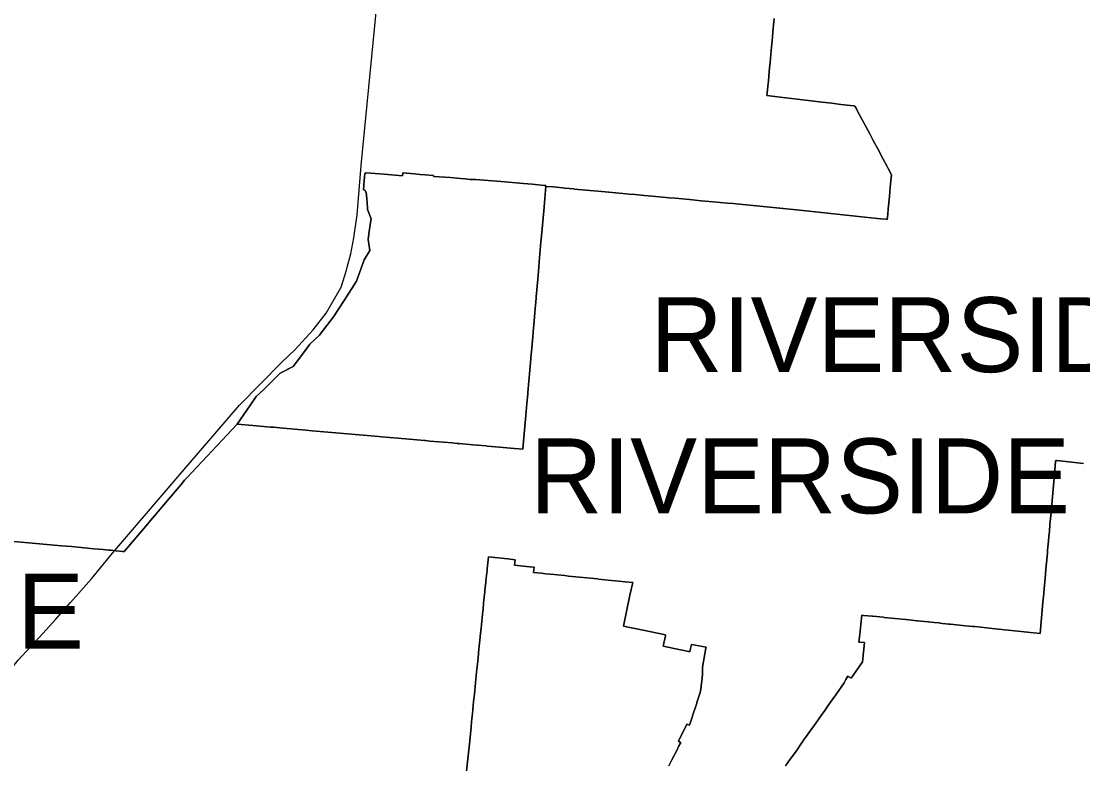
# Model space of a CAD drawing. Extents: x 0 to 34, y 0 to 22.
# Drawn here: x 5.5845 to 5.6984, y 15.4848 to 15.5644 of the extents above; entities that cross this region are included whole.
import ezdxf

# ---------------------------------------------------------------- set-up
doc = ezdxf.new("R2010")
doc.units = 0
for name, color, linetype in [('GM_X_Corporation', 7, 'Continuous'), ('GM_X_Corporation_Text', 7, 'Continuous'), ('GM_X_State_Route', 7, 'Continuous')]:
    doc.layers.add(name, color=color, linetype=linetype)

msp = doc.modelspace()

# ---------------------------------------------------------------- linework, layer by layer
at = {"layer": 'GM_X_Corporation'}
for points in [[(5.66528, 15.5647), (5.66525, 15.56436), (5.66518, 15.56366), (5.6651, 15.56277), (5.66509, 15.5627), (5.66496, 15.56127), (5.66484, 15.55999), (5.66478, 15.55939), (5.66475, 15.559), (5.66466, 15.55803), (5.6646, 15.55745), (5.66457, 15.55706), (5.66451, 15.55644), (5.66592, 15.55627), (5.66774, 15.55605), (5.66924, 15.55587), (5.67043, 15.55573), (5.67146, 15.55561), (5.67242, 15.55549), (5.67346, 15.55537), (5.67386, 15.55532), (5.67395, 15.55531), (5.67407, 15.55508), (5.67423, 15.55478), (5.6747, 15.5539), (5.67528, 15.55281), (5.6755, 15.55239), (5.67591, 15.55161), (5.67639, 15.55071), (5.67694, 15.54969), (5.6774, 15.54883), (5.67751, 15.5486), (5.67787, 15.54794), (5.67783, 15.54761), (5.67774, 15.54661), (5.67764, 15.54562), (5.67751, 15.54428), (5.67751, 15.5442), (5.67746, 15.54378), (5.67746, 15.54372), (5.67746, 15.54369), (5.67741, 15.54316), (5.67732, 15.54317), (5.67731, 15.54317), (5.67672, 15.54323), (5.67533, 15.54337), (5.67003, 15.54392), (5.66768, 15.54417), (5.66338, 15.54462), (5.66156, 15.54478), (5.66087, 15.54485), (5.66025, 15.5449), (5.65874, 15.54504), (5.65746, 15.54516), (5.65618, 15.54528), (5.65467, 15.54542), (5.65402, 15.54548), (5.65218, 15.54565), (5.65132, 15.54573), (5.65035, 15.54582), (5.64974, 15.54587), (5.64905, 15.54594), (5.64754, 15.54608), (5.64636, 15.54618), (5.64508, 15.5463), (5.64387, 15.54641), (5.64377, 15.54642), (5.64278, 15.54651), (5.64259, 15.54653), (5.64157, 15.54663), (5.64079, 15.5467), (5.64079, 15.54678), (5.6406, 15.5468), (5.6393, 15.54692), (5.63839, 15.547), (5.63599, 15.54721), (5.63505, 15.54729), (5.6337, 15.54741), (5.63329, 15.54744), (5.63285, 15.54744), (5.63269, 15.54744), (5.63266, 15.54744), (5.63214, 15.5475), (5.63162, 15.54754), (5.6313, 15.54757), (5.63056, 15.54763), (5.62874, 15.54777), (5.62875, 15.54785), (5.62783, 15.54793), (5.62732, 15.54798), (5.6267, 15.54803), (5.62544, 15.54815), (5.62541, 15.54782), (5.62503, 15.54786), (5.62343, 15.54799), (5.62152, 15.54815), (5.62151, 15.54815), (5.6215, 15.54815), (5.62149, 15.54815), (5.62148, 15.54815), (5.62147, 15.54815), (5.62146, 15.54814), (5.62145, 15.54814), (5.62144, 15.54814), (5.62144, 15.54813), (5.62143, 15.54813), (5.62142, 15.54812), (5.62141, 15.54812), (5.62141, 15.54811), (5.6214, 15.5481), (5.6214, 15.54809), (5.62139, 15.54809), (5.62139, 15.54808), (5.62138, 15.54807), (5.62138, 15.54806), (5.62138, 15.54805), (5.62137, 15.54804), (5.62137, 15.54803), (5.62131, 15.54732), (5.62121, 15.54631), (5.62137, 15.54629), (5.62152, 15.54603), (5.62157, 15.54539), (5.62165, 15.5444), (5.62167, 15.5442), (5.62203, 15.54323), (5.62197, 15.54283), (5.6218, 15.54162), (5.62172, 15.54099), (5.62192, 15.53981), (5.6213, 15.5388), (5.62049, 15.53654), (5.61915, 15.53445), (5.61801, 15.53271), (5.61656, 15.53084), (5.61649, 15.53075), (5.61545, 15.52977), (5.61489, 15.529), (5.61367, 15.52736), (5.61318, 15.52711), (5.61285, 15.52695), (5.61229, 15.52667), (5.61058, 15.52493), (5.61007, 15.52447), (5.60971, 15.52416), (5.60902, 15.52315), (5.60869, 15.52269), (5.60766, 15.52119), (5.60232, 15.51547), (5.60203, 15.51517), (5.60166, 15.51473), (5.60021, 15.51301), (5.59821, 15.51064), (5.59809, 15.51051), (5.5956, 15.50755), (5.59557, 15.50752), (5.59536, 15.50754), (5.5947, 15.5076), (5.59466, 15.5076), (5.5941, 15.50766), (5.59386, 15.50768), (5.59329, 15.50773), (5.59229, 15.50782), (5.58988, 15.50805), (5.58883, 15.50814), (5.58209, 15.50876)], [(5.58209, 15.50876), (5.58883, 15.50814), (5.58988, 15.50805), (5.59229, 15.50782), (5.59329, 15.50773), (5.59386, 15.50768), (5.5941, 15.50766), (5.59466, 15.5076), (5.5947, 15.5076), (5.59536, 15.50754), (5.59557, 15.50752), (5.5956, 15.50755), (5.59809, 15.51051), (5.59821, 15.51064), (5.60021, 15.51301), (5.60166, 15.51473), (5.60203, 15.51517), (5.60232, 15.51547), (5.60766, 15.52119), (5.60935, 15.52104), (5.61123, 15.52088), (5.61158, 15.52085), (5.61259, 15.52076), (5.61505, 15.52054), (5.6157, 15.52049), (5.62286, 15.51986), (5.62313, 15.51983), (5.62491, 15.51968), (5.62693, 15.5195), (5.62776, 15.51943), (5.62786, 15.51942), (5.62834, 15.51938), (5.62932, 15.51929), (5.63072, 15.51917), (5.63127, 15.51912), (5.6315, 15.5191), (5.63296, 15.51897), (5.63344, 15.51893), (5.63435, 15.51885), (5.63452, 15.51883), (5.63582, 15.51872), (5.637, 15.51861), (5.63832, 15.51849), (5.63843, 15.51974), (5.63854, 15.52092), (5.63864, 15.52213), (5.63875, 15.52341), (5.63884, 15.5244), (5.63886, 15.52458), (5.63896, 15.52579), (5.63906, 15.52697), (5.63917, 15.52818), (5.63918, 15.52826), (5.63927, 15.52939), (5.63938, 15.53056), (5.63946, 15.53156), (5.63948, 15.53177), (5.63961, 15.53317), (5.63974, 15.53471), (5.63975, 15.53484), (5.63992, 15.53674), (5.64003, 15.53802), (5.64008, 15.5386), (5.64026, 15.54073), (5.64029, 15.54098), (5.64059, 15.54446), (5.64063, 15.54496), (5.64079, 15.5467), (5.64157, 15.54663), (5.64259, 15.54653), (5.64278, 15.54651), (5.64377, 15.54642), (5.64387, 15.54641), (5.64508, 15.5463), (5.64636, 15.54618), (5.64754, 15.54608), (5.64905, 15.54594), (5.64974, 15.54587), (5.65035, 15.54582), (5.65132, 15.54573), (5.65218, 15.54565), (5.65402, 15.54548), (5.65467, 15.54542), (5.65618, 15.54528), (5.65746, 15.54516), (5.65874, 15.54504), (5.66025, 15.5449), (5.66087, 15.54485), (5.66156, 15.54478), (5.66338, 15.54462), (5.66768, 15.54417), (5.67003, 15.54392), (5.67533, 15.54337), (5.67672, 15.54323), (5.67731, 15.54317), (5.67732, 15.54317), (5.67741, 15.54316), (5.67746, 15.54369), (5.67746, 15.54372), (5.67746, 15.54378), (5.67751, 15.5442), (5.67751, 15.54428), (5.67764, 15.54562), (5.67774, 15.54661), (5.67783, 15.54761), (5.67787, 15.54794), (5.67751, 15.5486), (5.6774, 15.54883), (5.67694, 15.54969), (5.67639, 15.55071), (5.67591, 15.55161), (5.6755, 15.55239), (5.67528, 15.55281), (5.6747, 15.5539), (5.67423, 15.55478), (5.67407, 15.55508), (5.67395, 15.55531), (5.67386, 15.55532), (5.67346, 15.55537), (5.67242, 15.55549), (5.67146, 15.55561), (5.67043, 15.55573), (5.66924, 15.55587), (5.66774, 15.55605), (5.66592, 15.55627), (5.66451, 15.55644), (5.66457, 15.55706), (5.6646, 15.55745), (5.66466, 15.55803), (5.66475, 15.559), (5.66478, 15.55939), (5.66484, 15.55999), (5.66496, 15.56127), (5.66509, 15.5627), (5.6651, 15.56277), (5.66518, 15.56366), (5.66525, 15.56436), (5.66528, 15.5647)], [(5.6665, 15.48454), (5.66701, 15.48526), (5.66725, 15.48559), (5.66773, 15.48627), (5.66808, 15.48677), (5.66844, 15.48728), (5.66855, 15.48744), (5.66882, 15.48782), (5.66919, 15.48833), (5.66957, 15.48887), (5.66993, 15.48938), (5.6704, 15.49005), (5.67063, 15.49038), (5.67114, 15.4911), (5.67133, 15.49137), (5.67188, 15.49215), (5.6728, 15.49345), (5.67297, 15.49379), (5.67317, 15.49416), (5.67325, 15.49412), (5.6733, 15.49409), (5.67335, 15.49406), (5.67337, 15.49405), (5.6734, 15.49403), (5.67345, 15.494), (5.67349, 15.49397), (5.67354, 15.49394), (5.67429, 15.495), (5.67477, 15.49568), (5.67498, 15.49776), (5.67438, 15.49782), (5.67446, 15.49862), (5.67456, 15.49968), (5.67467, 15.5007), (5.67488, 15.50068), (5.6758, 15.50059), (5.67588, 15.50058), (5.677, 15.50047), (5.67708, 15.50046), (5.6782, 15.50034), (5.67826, 15.50034), (5.6794, 15.50022), (5.67943, 15.50022), (5.6806, 15.5001), (5.68064, 15.5001), (5.6818, 15.49998), (5.68185, 15.49997), (5.68246, 15.49991), (5.683, 15.49986), (5.68302, 15.49985), (5.68403, 15.49975), (5.6842, 15.49973), (5.6858, 15.49957), (5.6866, 15.49949), (5.68685, 15.49947), (5.68868, 15.49928), (5.69313, 15.49882), (5.69382, 15.49875), (5.69412, 15.50211), (5.6942, 15.50301), (5.69421, 15.50305), (5.69425, 15.50351), (5.69439, 15.50507), (5.69444, 15.50568), (5.6945, 15.5063), (5.69459, 15.50734), (5.69462, 15.50768), (5.69471, 15.50864), (5.69475, 15.50916), (5.6948, 15.50966), (5.69487, 15.51043), (5.69498, 15.5117), (5.6951, 15.51297), (5.6951, 15.51299), (5.69513, 15.51338), (5.69528, 15.51499), (5.69535, 15.51579), (5.69547, 15.51719), (5.69548, 15.51729), (5.69558, 15.51728), (5.69591, 15.51724), (5.69689, 15.51714), (5.69845, 15.51697)], [(5.69845, 15.51697), (5.69689, 15.51714), (5.69591, 15.51724), (5.69558, 15.51728), (5.69548, 15.51729), (5.69547, 15.51719), (5.69535, 15.51579), (5.69528, 15.51499), (5.69513, 15.51338), (5.6951, 15.51299), (5.6951, 15.51297), (5.69498, 15.5117), (5.69487, 15.51043), (5.6948, 15.50966), (5.69475, 15.50916), (5.69471, 15.50864), (5.69462, 15.50768), (5.69459, 15.50734), (5.6945, 15.5063), (5.69444, 15.50568), (5.69439, 15.50507), (5.69425, 15.50351), (5.69421, 15.50305), (5.6942, 15.50301), (5.69412, 15.50211), (5.69382, 15.49875), (5.69313, 15.49882), (5.68868, 15.49928), (5.68685, 15.49947), (5.6866, 15.49949), (5.6858, 15.49957), (5.6842, 15.49973), (5.68403, 15.49975), (5.68302, 15.49985), (5.683, 15.49986), (5.68246, 15.49991), (5.68185, 15.49997), (5.6818, 15.49998), (5.68064, 15.5001), (5.6806, 15.5001), (5.67943, 15.50022), (5.6794, 15.50022), (5.67826, 15.50034), (5.6782, 15.50034), (5.67708, 15.50046), (5.677, 15.50047), (5.67588, 15.50058), (5.6758, 15.50059), (5.67488, 15.50068), (5.67467, 15.5007), (5.67456, 15.49968), (5.67446, 15.49862), (5.67438, 15.49782), (5.67498, 15.49776), (5.67477, 15.49568), (5.67429, 15.495), (5.67354, 15.49394), (5.67349, 15.49397), (5.67345, 15.494), (5.6734, 15.49403), (5.67337, 15.49405), (5.67335, 15.49406), (5.6733, 15.49409), (5.67325, 15.49412), (5.67317, 15.49416), (5.67297, 15.49379), (5.6728, 15.49345), (5.67188, 15.49215), (5.67133, 15.49137), (5.67114, 15.4911), (5.67063, 15.49038), (5.6704, 15.49005), (5.66993, 15.48938), (5.66957, 15.48887), (5.66919, 15.48833), (5.66882, 15.48782), (5.66855, 15.48744), (5.66844, 15.48728), (5.66808, 15.48677), (5.66773, 15.48627), (5.66725, 15.48559), (5.66701, 15.48526), (5.6665, 15.48454)], [(5.63214, 15.48258), (5.63238, 15.48498), (5.63258, 15.48689), (5.63276, 15.48866), (5.63282, 15.4893), (5.63288, 15.48984), (5.63295, 15.49055), (5.633, 15.49101), (5.63304, 15.49145), (5.63312, 15.49222), (5.63324, 15.49343), (5.63328, 15.49383), (5.63329, 15.49387), (5.63336, 15.4946), (5.63342, 15.49515), (5.63348, 15.49578), (5.63352, 15.49611), (5.63361, 15.49706), (5.63374, 15.49834), (5.63375, 15.49841), (5.63387, 15.49962), (5.63388, 15.49966), (5.63399, 15.50079), (5.634, 15.50083), (5.63405, 15.50135), (5.63411, 15.50197), (5.63421, 15.50295), (5.63424, 15.50318), (5.63425, 15.50334), (5.63435, 15.50423), (5.63436, 15.50438), (5.63448, 15.50552), (5.63449, 15.50566), (5.63462, 15.50694), (5.6367, 15.50673), (5.6375, 15.50665), (5.63744, 15.50605), (5.63904, 15.50589), (5.63952, 15.50584), (5.63946, 15.50528), (5.64031, 15.50519), (5.64074, 15.50515), (5.64167, 15.50506), (5.64202, 15.50502), (5.64284, 15.50494), (5.64323, 15.5049), (5.64402, 15.50482), (5.6444, 15.50478), (5.64519, 15.5047), (5.64637, 15.50458), (5.64645, 15.50457), (5.64782, 15.50443), (5.64862, 15.50435), (5.64929, 15.50428), (5.6501, 15.5042), (5.64981, 15.50284), (5.64911, 15.49951), (5.65016, 15.49929), (5.65122, 15.49908), (5.65363, 15.49858), (5.65361, 15.49849), (5.65338, 15.49738), (5.65522, 15.49699), (5.65546, 15.49694), (5.65623, 15.49678), (5.65624, 15.49681), (5.65631, 15.49713), (5.6564, 15.49757), (5.65798, 15.49725), (5.65796, 15.49717), (5.65759, 15.49513), (5.6576, 15.49472), (5.6576, 15.49467), (5.6576, 15.49432), (5.65752, 15.49366), (5.65736, 15.49254), (5.65729, 15.49231), (5.657, 15.49133), (5.65698, 15.49127), (5.65687, 15.49093), (5.6566, 15.49011), (5.65645, 15.48966), (5.6562, 15.48889), (5.65591, 15.489), (5.65501, 15.48718), (5.65514, 15.48712), (5.65527, 15.48705), (5.65503, 15.4866), (5.6549, 15.48634), (5.6543, 15.48518), (5.65397, 15.48454)], [(5.65397, 15.48454), (5.6543, 15.48518), (5.6549, 15.48634), (5.65503, 15.4866), (5.65527, 15.48705), (5.65514, 15.48712), (5.65501, 15.48718), (5.65591, 15.489), (5.6562, 15.48889), (5.65645, 15.48966), (5.6566, 15.49011), (5.65687, 15.49093), (5.65698, 15.49127), (5.657, 15.49133), (5.65729, 15.49231), (5.65736, 15.49254), (5.65752, 15.49366), (5.6576, 15.49432), (5.6576, 15.49467), (5.6576, 15.49472), (5.65759, 15.49513), (5.65796, 15.49717), (5.65798, 15.49725), (5.6564, 15.49757), (5.65631, 15.49713), (5.65624, 15.49681), (5.65623, 15.49678), (5.65546, 15.49694), (5.65522, 15.49699), (5.65338, 15.49738), (5.65361, 15.49849), (5.65363, 15.49858), (5.65122, 15.49908), (5.65016, 15.49929), (5.64911, 15.49951), (5.64981, 15.50284), (5.6501, 15.5042), (5.64929, 15.50428), (5.64862, 15.50435), (5.64782, 15.50443), (5.64781, 15.50443), (5.64645, 15.50457), (5.64637, 15.50458), (5.64519, 15.5047), (5.6444, 15.50478), (5.64402, 15.50482), (5.64323, 15.5049), (5.64284, 15.50494), (5.64202, 15.50502), (5.64167, 15.50506), (5.64074, 15.50515), (5.64031, 15.50519), (5.63946, 15.50528), (5.63952, 15.50584), (5.63904, 15.50589), (5.63744, 15.50605), (5.6375, 15.50665), (5.6367, 15.50673), (5.63462, 15.50694), (5.63449, 15.50566), (5.63448, 15.50552), (5.63436, 15.50438), (5.63435, 15.50423), (5.63425, 15.50334), (5.63424, 15.50318), (5.63421, 15.50295), (5.63411, 15.50197), (5.63405, 15.50135), (5.63405, 15.50131), (5.634, 15.50083), (5.63399, 15.50079), (5.63388, 15.49966), (5.63387, 15.49962), (5.63375, 15.49841), (5.63374, 15.49834), (5.63361, 15.49706), (5.63352, 15.49611), (5.63348, 15.49578), (5.63342, 15.49515), (5.63336, 15.4946), (5.63329, 15.49387), (5.63328, 15.49383), (5.63324, 15.49343), (5.63312, 15.49222), (5.63304, 15.49145), (5.633, 15.49101), (5.63295, 15.49055), (5.63288, 15.48984), (5.63282, 15.4893), (5.63276, 15.48866), (5.63258, 15.48689), (5.63238, 15.48498), (5.63214, 15.48258)]]:
    msp.add_lwpolyline(points, dxfattribs=at)
msp.add_lwpolyline([(5.60766, 15.52119), (5.60869, 15.52269), (5.60902, 15.52315), (5.60971, 15.52416), (5.61007, 15.52447), (5.61058, 15.52493), (5.61229, 15.52667), (5.61285, 15.52695), (5.61367, 15.52736), (5.61489, 15.529), (5.61545, 15.52977), (5.61649, 15.53075), (5.61656, 15.53084), (5.61801, 15.53271), (5.61915, 15.53445), (5.62049, 15.53654), (5.6213, 15.5388), (5.62192, 15.53981), (5.62172, 15.54099), (5.6218, 15.54162), (5.62197, 15.54283), (5.62203, 15.54323), (5.62167, 15.5442), (5.62165, 15.5444), (5.62157, 15.54539), (5.62152, 15.54603), (5.62137, 15.54629), (5.62121, 15.54631), (5.62131, 15.54732), (5.62137, 15.54803), (5.62137, 15.54804), (5.62138, 15.54805), (5.62138, 15.54806), (5.62138, 15.54807), (5.62139, 15.54808), (5.62139, 15.54809), (5.6214, 15.54809), (5.6214, 15.5481), (5.62141, 15.54811), (5.62141, 15.54812), (5.62142, 15.54812), (5.62143, 15.54813), (5.62144, 15.54813), (5.62144, 15.54814), (5.62145, 15.54814), (5.62146, 15.54814), (5.62147, 15.54815), (5.62148, 15.54815), (5.62149, 15.54815), (5.6215, 15.54815), (5.62151, 15.54815), (5.62152, 15.54815), (5.62343, 15.54799), (5.62503, 15.54786), (5.62541, 15.54782), (5.62544, 15.54815), (5.6267, 15.54803), (5.62732, 15.54798), (5.62783, 15.54793), (5.62875, 15.54785), (5.62874, 15.54777), (5.63056, 15.54763), (5.6313, 15.54757), (5.63162, 15.54754), (5.63214, 15.5475), (5.63266, 15.54744), (5.63285, 15.54744), (5.63289, 15.54744), (5.63327, 15.54744), (5.63329, 15.54744), (5.6337, 15.54741), (5.63505, 15.54729), (5.63599, 15.54721), (5.63839, 15.547), (5.6393, 15.54692), (5.6406, 15.5468), (5.64079, 15.54678), (5.64079, 15.5467), (5.64063, 15.54496), (5.64059, 15.54446), (5.64029, 15.54098), (5.6403, 15.54098), (5.64026, 15.54073), (5.64008, 15.5386), (5.64003, 15.53802), (5.63992, 15.53674), (5.63975, 15.53484), (5.63974, 15.53471), (5.63961, 15.53317), (5.63948, 15.53177), (5.63946, 15.53156), (5.63938, 15.53056), (5.63927, 15.52939), (5.63918, 15.52826), (5.63917, 15.52818), (5.63906, 15.52697), (5.63896, 15.52579), (5.63886, 15.52458), (5.63884, 15.5244), (5.63875, 15.52341), (5.63864, 15.52213), (5.63854, 15.52092), (5.63843, 15.51974), (5.63832, 15.51849), (5.637, 15.51861), (5.63582, 15.51872), (5.63452, 15.51883), (5.63435, 15.51885), (5.63344, 15.51893), (5.63296, 15.51897), (5.6315, 15.5191), (5.63127, 15.51912), (5.63072, 15.51917), (5.62932, 15.51929), (5.62834, 15.51938), (5.62786, 15.51942), (5.62776, 15.51943), (5.62693, 15.5195), (5.62491, 15.51968), (5.62313, 15.51983), (5.62305, 15.51984), (5.62286, 15.51986), (5.6157, 15.52049), (5.61505, 15.52054), (5.61259, 15.52076), (5.61158, 15.52085), (5.61123, 15.52088), (5.60935, 15.52104)], close=True, dxfattribs=at)
at = {"layer": 'GM_X_State_Route'}
for points in [[(5.62097, 15.54895), (5.62309, 15.57055), (5.6234, 15.57374), (5.62378, 15.57814), (5.6247, 15.58677), (5.62565, 15.59848), (5.62609, 15.60031), (5.62643, 15.60135), (5.62694, 15.60247), (5.62955, 15.60668), (5.63349, 15.61287), (5.63687, 15.61836), (5.63897, 15.62168), (5.63966, 15.62289), (5.64344, 15.63235), (5.64829, 15.64395), (5.65026, 15.64896), (5.65278, 15.65527), (5.65574, 15.66279), (5.65676, 15.66542), (5.65708, 15.66628), (5.6583, 15.66849), (5.65858, 15.66902)], [(5.61948, 15.53803), (5.61988, 15.53946), (5.62017, 15.54116), (5.62054, 15.54363), (5.62097, 15.54895)], [(5.59428, 15.50734), (5.59471, 15.50786), (5.60241, 15.51681), (5.60792, 15.52321), (5.61247, 15.52785), (5.61384, 15.52915), (5.61583, 15.5313), (5.61723, 15.53311), (5.61884, 15.5359), (5.61939, 15.53771), (5.61948, 15.53803)], [(5.5882, 15.50027), (5.58979, 15.50204), (5.59205, 15.50459), (5.59428, 15.50734)], [(5.57561, 15.48518), (5.57571, 15.48531), (5.57688, 15.48691), (5.58167, 15.49283), (5.58416, 15.49587), (5.58683, 15.49875), (5.5882, 15.50027)]]:
    msp.add_lwpolyline(points, dxfattribs=at)

# ---------------------------------------------------------------- texts
at = {"layer": 'GM_X_Corporation_Text'}
for p in [(5.652, 15.52677), (5.63909, 15.51162), (5.53329, 15.49712)]:
    msp.add_text('RIVERSIDE', height=0.008037, rotation=0, dxfattribs=at).set_placement(p)

doc.saveas('drawing.dxf')
